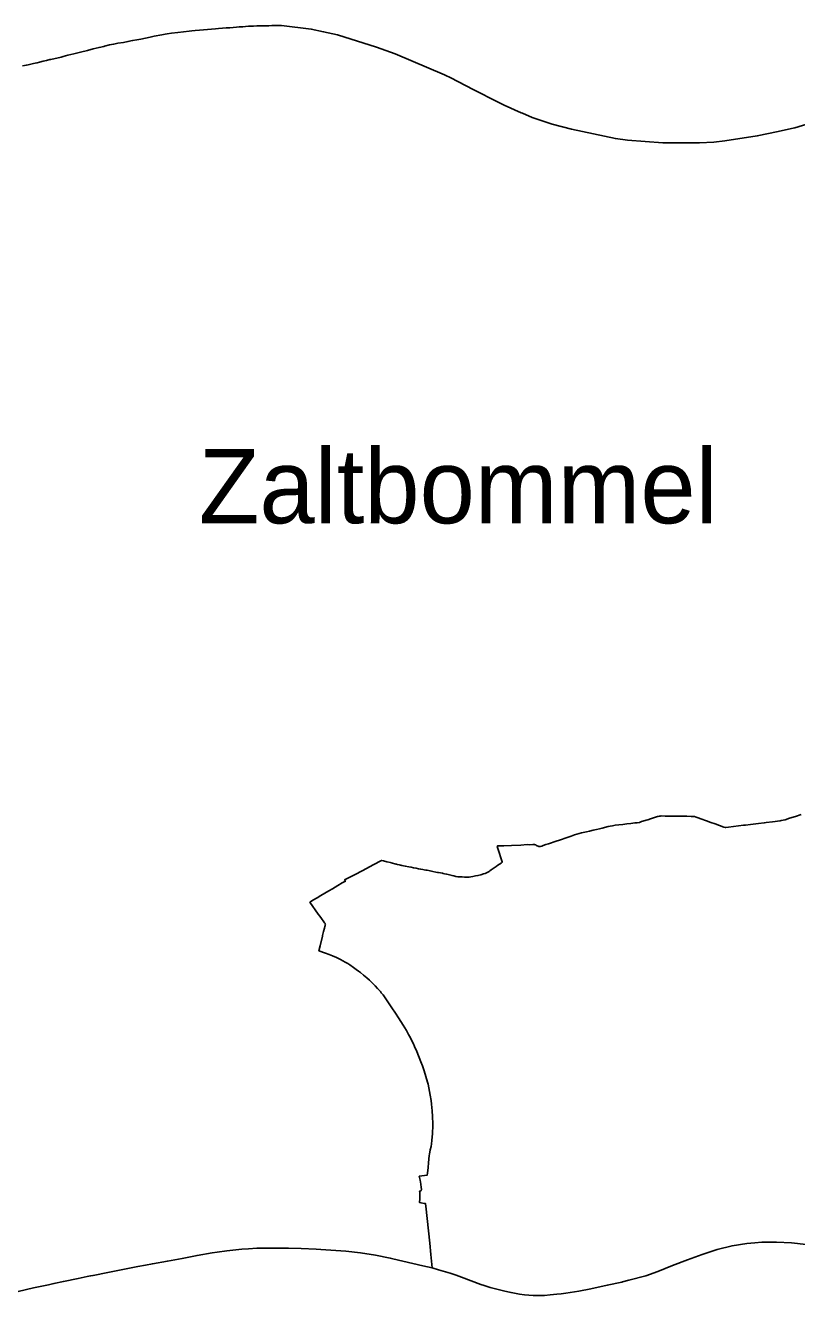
# Model space of a CAD drawing. Extents: x 113371 to 291721, y 393993 to 520143.
# Drawn here: x 138319 to 143509, y 416873 to 425419 of the extents above; entities that cross this region are included whole.
import ezdxf

# ---------------------------------------------------------------- set-up
doc = ezdxf.new("R2010")
doc.units = 0
doc.layers.add('Default', color=7, linetype='Continuous')
doc.layers.add('plaatsnamen', color=7, linetype='Continuous')

msp = doc.modelspace()

# ---------------------------------------------------------------- linework, layer by layer
at = {"layer": 'Default'}
for points in [[(139301.265625, 425366.0325), (139272.555625, 425362.2925), (139258.415625, 425360.2925), (139237.305625, 425356.3025), (139185.835625, 425346.1025), (139158.485625, 425340.3625), (139095.685625, 425327.6925), (139068.735625, 425322.7525), (139039.975625, 425317.1125), (139008.925625, 425311.0525), (138977.775625, 425305.3925), (138940.525625, 425298.7925), (138913.575625, 425293.9525), (138898.645625, 425291.0525), (138884.625625, 425287.6125), (138851.785625, 425279.5925), (138846.865625, 425278.4725), (138814.605625, 425271.1325), (138775.585625, 425261.2225), (138736.615625, 425251.3125), (138690.405625, 425240.1425), (138644.995625, 425228.5925), (138605.225625, 425218.5225), (138572.735625, 425210.5525), (138558.425625, 425206.6525), (138488.975625, 425190.7925), (138483.985625, 425189.4125), (138461.015625, 425184.3125), (138437.445625, 425178.1925), (138413.925625, 425172.2125), (138397.695625, 425168.5325), (138383.685625, 425165.0725), (138372.415625, 425162.3525), (138354.205625, 425158.0825), (138338.215625, 425154.2825), (138325.685625, 425152.2925), (138298.225625, 425147.3425)], [(138354.205625, 425158.0825), (138372.415625, 425162.3525), (138383.685625, 425165.0725), (138397.695625, 425168.5325), (138413.925625, 425172.2125), (138437.445625, 425178.1925), (138461.015625, 425184.3125), (138483.985625, 425189.4125), (138488.975625, 425190.7925), (138558.425625, 425206.6525), (138572.735625, 425210.5525), (138605.225625, 425218.5225), (138644.995625, 425228.5925), (138690.405625, 425240.1425), (138736.615625, 425251.3125), (138775.585625, 425261.2225), (138814.605625, 425271.1325), (138846.865625, 425278.4725), (138851.785625, 425279.5925), (138884.625625, 425287.6125), (138898.645625, 425291.0525), (138913.575625, 425293.9525), (138940.525625, 425298.7925), (138977.775625, 425305.3925), (139008.925625, 425311.0525), (139039.975625, 425317.1125), (139068.735625, 425322.7525), (139095.685625, 425327.6925), (139158.485625, 425340.3625), (139185.835625, 425346.1025), (139237.305625, 425356.3025), (139258.415625, 425360.2925), (139272.555625, 425362.2925), (139301.265625, 425366.0325), (139343.525625, 425371.3725), (139383.025625, 425376.5325), (139421.635625, 425381.5025), (139438.215625, 425383.1125)], [(141138.875625, 425087.6325), (140806.155625, 425227.5025), (140681.085625, 425272.8225), (140418.285625, 425356.1225), (140325.295625, 425376.2825), (140242.585625, 425394.2125), (140042.085625, 425419.3625), (140022.125625, 425418.4725), (139999.185625, 425418.0725), (139977.995625, 425417.7725), (139957.705625, 425417.3825), (139940.715625, 425416.7725), (139919.465625, 425416.3825), (139899.125625, 425416.0925), (139877.035625, 425415.4925), (139853.945625, 425414.9325), (139836.805625, 425414.6625), (139820.615625, 425413.6525), (139799.725625, 425412.0125), (139781.095625, 425410.7425), (139758.355625, 425409.0325), (139738.275625, 425407.5925), (139716.285625, 425405.9525), (139693.905625, 425403.9425), (139669.075625, 425402.3825), (139644.845625, 425400.4625), (139619.115625, 425398.5425), (139599.035625, 425396.9025), (139571.755625, 425394.5225), (139544.825625, 425392.1325), (139517.395625, 425389.8025), (139489.675625, 425387.5125), (139460.895625, 425385.0625), (139438.215625, 425383.1125), (139421.635625, 425381.5025), (139383.025625, 425376.5325), (139343.525625, 425371.3725), (139301.265625, 425366.0325)], [(139438.215625, 425383.1125), (139460.895625, 425385.0625), (139489.675625, 425387.5125), (139517.395625, 425389.8025), (139544.825625, 425392.1325), (139571.755625, 425394.5225), (139599.035625, 425396.9025), (139619.115625, 425398.5425), (139644.845625, 425400.4625), (139669.075625, 425402.3825), (139693.905625, 425403.9425), (139716.285625, 425405.9525), (139738.275625, 425407.5925), (139758.355625, 425409.0325), (139781.095625, 425410.7425), (139799.725625, 425412.0125), (139820.615625, 425413.6525), (139836.805625, 425414.6625), (139853.945625, 425414.9325), (139877.035625, 425415.4925), (139899.125625, 425416.0925), (139919.465625, 425416.3825), (139940.715625, 425416.7725), (139957.705625, 425417.3825), (139977.995625, 425417.7725), (139999.185625, 425418.0725), (140022.125625, 425418.4725), (140042.085625, 425419.3625), (140242.585625, 425394.2125), (140325.295625, 425376.2825), (140418.285625, 425356.1225), (140681.085625, 425272.8225), (140806.155625, 425227.5025), (141138.875625, 425087.6325), (141147.575625, 425083.1625), (141177.265625, 425067.9125), (141337.445625, 424985.6325), (141495.245625, 424904.1225)], [(138298.225625, 425147.3425), (138325.685625, 425152.2925), (138338.215625, 425154.2825), (138354.205625, 425158.0825)], [(143755.485625, 424807.6025), (143498.085625, 424729.8025), (143474.845625, 424724.8625), (143385.995625, 424705.9525), (143244.285625, 424675.7925), (143026.015625, 424642.0825), (142952.685625, 424634.5925), (142855.895625, 424629.1425), (142799.045625, 424629.1625), (142608.115625, 424629.2325), (142371.875625, 424648.0225), (142290.035625, 424657.5625), (141994.255625, 424720.2725), (141863.845625, 424755.2625), (141755.985625, 424790.8125), (141728.415625, 424800.2025), (141664.665625, 424828.0625), (141655.935625, 424831.8825), (141541.905625, 424883.1425), (141495.245625, 424904.1225), (141337.445625, 424985.6325), (141177.265625, 425067.9125), (141147.575625, 425083.1625), (141138.875625, 425087.6325)], [(141495.245625, 424904.1225), (141541.905625, 424883.1425), (141655.935625, 424831.8825), (141664.665625, 424828.0625), (141728.415625, 424800.2025), (141755.985625, 424790.8125), (141863.845625, 424755.2625), (141994.255625, 424720.2725), (142290.035625, 424657.5625), (142371.875625, 424648.0225), (142608.115625, 424629.2325), (142799.045625, 424629.1625), (142855.895625, 424629.1425), (142952.685625, 424634.5925), (143026.015625, 424642.0825), (143244.285625, 424675.7925), (143385.995625, 424705.9525), (143474.845625, 424724.8625), (143498.085625, 424729.8025), (143755.485625, 424807.6025)], [(141779.245625, 419893.8925), (141783.885625, 419893.8925), (141794.665625, 419896.9625), (141803.615625, 419900.4325), (141821.995625, 419907.1925), (141840.015625, 419912.6725), (141890.015625, 419930.4925), (141912.195625, 419937.6925), (141964.845625, 419955.6425), (141991.115625, 419964.7025), (142013.145625, 419972.1825), (142029.825625, 419977.3525), (142045.125625, 419981.8925), (142062.095625, 419986.2025), (142094.735625, 419993.1925), (142114.445625, 419997.9325), (142140.935625, 420004.6825), (142162.855625, 420010.0525), (142181.345625, 420014.4925), (142200.315625, 420019.2325), (142241.615625, 420028.3625), (142253.255625, 420030.7625), (142269.955625, 420034.3125), (142287.495625, 420037.2525), (142312.285625, 420040.1225), (142338.685625, 420043.4625), (142366.605625, 420046.7925), (142394.265625, 420049.6525), (142419.955625, 420053.0425), (142436.265625, 420054.9425), (142451.105625, 420057.1425), (142460.965625, 420060.5025), (142466.065625, 420062.0525), (142474.195625, 420064.3225), (142495.745625, 420070.9025), (142507.825625, 420074.6925), (142525.465625, 420080.3925), (142572.875625, 420095.6325)], [(143050.675625, 420024.8525), (143050.185625, 420024.7925), (143032.385625, 420022.4925), (143029.155625, 420022.0725), (143029.155625, 420022.0625), (143020.205625, 420025.3325), (142990.665625, 420036.0625), (142961.145625, 420046.5225), (142932.855625, 420056.6225), (142901.685625, 420067.7025), (142888.815625, 420072.2725), (142878.095625, 420076.0925), (142832.345625, 420092.3525), (142822.895625, 420095.7125), (142820.605625, 420096.5325), (142814.065625, 420096.7225), (142798.545625, 420097.1825), (142771.045625, 420098.0125), (142731.365625, 420099.1925), (142701.265625, 420098.7525), (142659.505625, 420099.7225), (142624.815625, 420099.6625), (142597.105625, 420100.0325), (142590.565625, 420099.8225), (142585.385625, 420098.9125), (142577.965625, 420097.0125), (142572.875625, 420095.6325), (142525.465625, 420080.3925), (142507.825625, 420074.6925), (142495.745625, 420070.9025), (142474.195625, 420064.3225), (142466.065625, 420062.0525), (142460.965625, 420060.5025), (142451.105625, 420057.1425), (142436.265625, 420054.9425), (142419.955625, 420053.0425), (142394.265625, 420049.6525), (142366.605625, 420046.7925)], [(142572.875625, 420095.6325), (142577.965625, 420097.0125), (142585.385625, 420098.9125), (142590.565625, 420099.8225), (142597.105625, 420100.0325), (142624.815625, 420099.6625), (142659.505625, 420099.7225), (142701.265625, 420098.7525), (142731.365625, 420099.1925), (142771.045625, 420098.0125), (142798.545625, 420097.1825), (142814.065625, 420096.7225), (142820.605625, 420096.5325), (142822.895625, 420095.7125), (142832.345625, 420092.3525), (142878.095625, 420076.0925), (142888.815625, 420072.2725), (142901.685625, 420067.7025), (142932.855625, 420056.6225), (142961.145625, 420046.5225), (142990.665625, 420036.0625), (143020.205625, 420025.3325), (143029.155625, 420022.0625), (143029.155625, 420022.0725), (143032.385625, 420022.4925), (143050.185625, 420024.7925), (143050.675625, 420024.8525), (143152.135625, 420037.9325), (143165.445625, 420038.9625), (143199.095625, 420043.5225), (143252.145625, 420049.9025), (143290.585625, 420054.7425), (143291.875625, 420054.9125), (143304.385625, 420056.4825), (143304.955625, 420056.5625), (143347.875625, 420061.6125), (143398.275625, 420068.4325), (143405.795625, 420069.6925)], [(143540.075625, 420109.6925), (143500.735625, 420097.4925), (143460.325625, 420084.3125), (143433.085625, 420075.1925), (143405.795625, 420069.6925), (143398.275625, 420068.4325), (143347.875625, 420061.6125), (143304.955625, 420056.5625), (143304.385625, 420056.4825), (143291.875625, 420054.9125), (143290.585625, 420054.7425), (143252.145625, 420049.9025), (143199.095625, 420043.5225), (143165.445625, 420038.9625), (143152.135625, 420037.9325), (143050.675625, 420024.8525)], [(143405.795625, 420069.6925), (143433.085625, 420075.1925), (143460.325625, 420084.3125), (143500.735625, 420097.4925), (143540.075625, 420109.6925)], [(142366.605625, 420046.7925), (142338.685625, 420043.4625), (142312.285625, 420040.1225), (142287.495625, 420037.2525), (142269.955625, 420034.3125), (142253.255625, 420030.7625), (142241.615625, 420028.3625), (142200.315625, 420019.2325), (142181.345625, 420014.4925), (142162.855625, 420010.0525), (142140.935625, 420004.6825), (142114.445625, 419997.9325), (142094.735625, 419993.1925), (142062.095625, 419986.2025), (142045.125625, 419981.8925), (142029.825625, 419977.3525), (142013.145625, 419972.1825), (141991.115625, 419964.7025), (141964.845625, 419955.6425), (141912.195625, 419937.6925), (141890.015625, 419930.4925), (141840.015625, 419912.6725), (141821.995625, 419907.1925), (141803.615625, 419900.4325), (141794.665625, 419896.9625), (141783.885625, 419893.8925), (141779.245625, 419893.8925), (141775.135625, 419895.2625), (141769.445625, 419897.1625), (141763.755625, 419899.5825), (141758.145625, 419902.5425), (141752.875625, 419904.9625), (141749.085625, 419906.4325), (141743.915625, 419907.3825), (141739.695625, 419907.9125), (141734.855625, 419907.9125), (141710.775625, 419907.0625), (141696.745625, 419907.4825)], [(141696.745625, 419907.4825), (141652.645625, 419904.8625), (141589.235625, 419902.0925), (141538.275625, 419900.1025), (141494.985625, 419899.1225), (141496.235625, 419895.4525), (141494.195625, 419895.3625), (141494.435625, 419894.6325), (141505.195625, 419861.6425), (141520.745625, 419811.0425), (141526.885625, 419791.8925), (141527.055625, 419791.3625), (141528.055625, 419788.2625), (141520.135625, 419782.9525), (141510.205625, 419775.8925), (141498.685625, 419768.1425), (141486.655625, 419759.8925), (141472.875625, 419750.3525), (141453.975625, 419737.3325), (141445.455625, 419731.5225), (141439.195625, 419727.0925), (141434.575625, 419723.8125), (141425.515625, 419719.2525), (141413.945625, 419713.6025), (141411.295625, 419712.6625), (141401.935625, 419710.0525), (141382.775625, 419704.4825), (141364.555625, 419699.1125), (141348.855625, 419696.5725), (141329.495625, 419693.1525), (141315.395625, 419690.9125), (141306.035625, 419689.4525), (141288.745625, 419688.5725), (141274.645625, 419688.9325), (141257.105625, 419689.6125), (141236.665625, 419690.3425), (141228.375625, 419690.8325), (141215.685625, 419692.6325)], [(141382.775625, 419704.4825), (141401.935625, 419710.0525), (141411.295625, 419712.6625), (141413.945625, 419713.6025), (141425.515625, 419719.2525), (141434.575625, 419723.8125), (141439.195625, 419727.0925), (141445.455625, 419731.5225), (141453.975625, 419737.3325), (141472.875625, 419750.3525), (141486.655625, 419759.8925), (141498.685625, 419768.1425), (141510.205625, 419775.8925), (141520.135625, 419782.9525), (141528.055625, 419788.2625), (141527.055625, 419791.3625), (141526.885625, 419791.8925), (141520.745625, 419811.0425), (141505.195625, 419861.6425), (141494.435625, 419894.6325), (141494.195625, 419895.3625), (141496.235625, 419895.4525), (141494.985625, 419899.1225), (141538.275625, 419900.1025), (141589.235625, 419902.0925), (141652.645625, 419904.8625), (141696.745625, 419907.4825), (141710.775625, 419907.0625), (141734.855625, 419907.9125), (141739.695625, 419907.9125), (141743.915625, 419907.3825), (141749.085625, 419906.4325), (141752.875625, 419904.9625), (141758.145625, 419902.5425), (141763.755625, 419899.5825), (141769.445625, 419897.1625), (141775.135625, 419895.2625), (141779.245625, 419893.8925)], [(140327.305625, 419387.4725), (140310.785625, 419410.5925), (140299.895625, 419425.9825), (140289.765625, 419440.5725), (140233.665625, 419520.8425), (140234.835625, 419521.5425), (140237.345625, 419523.0225), (140253.695625, 419532.6925), (140282.475625, 419549.7325), (140307.205625, 419564.3725), (140333.775625, 419580.0925), (140361.045625, 419596.2325), (140385.625625, 419610.7825), (140420.395625, 419631.3525), (140451.575625, 419649.8025), (140459.275625, 419654.3625), (140472.195625, 419661.1125), (140466.545625, 419669.4325), (140466.395625, 419669.6525), (140532.665625, 419704.5225), (140588.755625, 419734.2725), (140658.325625, 419771.0625), (140716.265625, 419801.5525), (140728.125625, 419798.3925), (140751.695625, 419792.4425), (140775.175625, 419786.2825), (140777.455625, 419785.6825), (140779.625625, 419785.1225), (140813.005625, 419776.3925), (140819.095625, 419774.8325), (140821.025625, 419774.3425), (140836.415625, 419770.4225), (140839.515625, 419769.6325), (140842.175625, 419769.0725), (140844.695625, 419768.5525), (140851.955625, 419767.0325), (140852.215625, 419766.9825), (140875.375625, 419762.5825)], [(140777.455625, 419785.6825), (140775.175625, 419786.2825), (140751.695625, 419792.4425), (140728.125625, 419798.3925), (140716.265625, 419801.5525), (140658.325625, 419771.0625), (140588.755625, 419734.2725), (140532.665625, 419704.5225), (140466.395625, 419669.6525), (140466.545625, 419669.4325), (140472.195625, 419661.1125), (140459.275625, 419654.3625), (140451.575625, 419649.8025), (140420.395625, 419631.3525), (140385.625625, 419610.7825), (140361.045625, 419596.2325), (140333.775625, 419580.0925), (140307.205625, 419564.3725), (140282.475625, 419549.7325), (140253.695625, 419532.6925), (140237.345625, 419523.0225), (140234.835625, 419521.5425), (140233.665625, 419520.8425), (140289.765625, 419440.5725), (140299.895625, 419425.9825), (140310.785625, 419410.5925), (140327.305625, 419387.4725), (140331.535625, 419381.4825), (140335.535625, 419375.8225), (140336.795625, 419374.0425), (140337.975625, 419372.3625), (140336.945625, 419368.1825), (140336.715625, 419367.2725), (140335.045625, 419360.5225), (140333.885625, 419355.8525), (140331.275625, 419345.3525), (140325.555625, 419322.2925), (140318.855625, 419295.3325)], [(141215.685625, 419692.6325), (141201.855625, 419696.4825), (141189.775625, 419699.5425), (141172.595625, 419704.2625), (141163.155625, 419706.9425), (141153.575625, 419709.0825), (141139.835625, 419711.7425), (141130.045625, 419713.9325), (141125.555625, 419714.8525), (141113.265625, 419716.7525), (141098.735625, 419719.2625), (141092.535625, 419720.2425), (141081.145625, 419722.4325), (141061.175625, 419726.4725), (141041.895625, 419730.3425), (141022.615625, 419734.5225), (141013.125625, 419736.3125), (141002.185625, 419738.3625), (140992.395625, 419740.1525), (140978.515625, 419742.6125), (140965.075625, 419744.9125), (140948.795625, 419748.1825), (140931.365625, 419751.4525), (140931.285625, 419751.4725), (140914.385625, 419754.8225), (140898.105625, 419758.0925), (140875.375625, 419762.5825), (140852.215625, 419766.9825), (140851.955625, 419767.0325), (140844.695625, 419768.5525), (140842.175625, 419769.0725), (140839.515625, 419769.6325), (140836.415625, 419770.4225), (140821.025625, 419774.3425), (140819.095625, 419774.8325), (140813.005625, 419776.3925), (140779.625625, 419785.1225), (140777.455625, 419785.6825)], [(140875.375625, 419762.5825), (140898.105625, 419758.0925), (140914.385625, 419754.8225), (140931.285625, 419751.4725), (140931.365625, 419751.4525), (140948.795625, 419748.1825), (140965.075625, 419744.9125), (140978.515625, 419742.6125), (140992.395625, 419740.1525), (141002.185625, 419738.3625), (141013.125625, 419736.3125), (141022.615625, 419734.5225), (141041.895625, 419730.3425), (141061.175625, 419726.4725), (141081.145625, 419722.4325), (141092.535625, 419720.2425), (141098.735625, 419719.2625), (141113.265625, 419716.7525), (141125.555625, 419714.8525), (141130.045625, 419713.9325), (141139.835625, 419711.7425), (141153.575625, 419709.0825), (141163.155625, 419706.9425), (141172.595625, 419704.2625), (141189.775625, 419699.5425), (141201.855625, 419696.4825), (141215.685625, 419692.6325), (141228.375625, 419690.8325), (141236.665625, 419690.3425), (141257.105625, 419689.6125), (141274.645625, 419688.9325), (141288.745625, 419688.5725), (141306.035625, 419689.4525), (141315.395625, 419690.9125), (141329.495625, 419693.1525), (141348.855625, 419696.5725), (141364.555625, 419699.1125), (141382.775625, 419704.4825)], [(140735.005625, 418883.6625), (140725.865625, 418895.6525), (140713.985625, 418911.2925), (140707.965625, 418919.0225), (140689.065625, 418938.4125), (140671.715625, 418956.8125), (140649.955625, 418979.0825), (140633.625625, 418994.9125), (140616.265625, 419010.4525), (140594.835625, 419028.4825), (140573.445625, 419046.1625), (140560.145625, 419056.3725), (140544.455625, 419067.8025), (140526.165625, 419080.6725), (140501.235625, 419098.4525), (140487.705625, 419107.0325), (140470.625625, 419117.3625), (140455.325625, 419125.9125), (140439.455625, 419134.2625), (140411.555625, 419147.2125), (140385.705625, 419158.2625), (140362.285625, 419167.6525), (140338.415625, 419176.5425), (140294.355625, 419192.8225), (140302.245625, 419225.8725), (140317.815625, 419291.1425), (140318.855625, 419295.3325), (140325.555625, 419322.2925), (140331.275625, 419345.3525), (140333.885625, 419355.8525), (140335.045625, 419360.5225), (140336.715625, 419367.2725), (140336.945625, 419368.1825), (140337.975625, 419372.3625), (140336.795625, 419374.0425), (140335.535625, 419375.8225), (140331.535625, 419381.4825), (140327.305625, 419387.4725)], [(140318.855625, 419295.3325), (140317.815625, 419291.1425), (140302.245625, 419225.8725), (140294.355625, 419192.8225), (140338.415625, 419176.5425), (140362.285625, 419167.6525), (140385.705625, 419158.2625), (140411.555625, 419147.2125), (140439.455625, 419134.2625), (140455.325625, 419125.9125), (140470.625625, 419117.3625), (140487.705625, 419107.0325), (140501.235625, 419098.4525), (140526.165625, 419080.6725), (140544.455625, 419067.8025), (140560.145625, 419056.3725), (140573.445625, 419046.1625), (140594.835625, 419028.4825), (140616.265625, 419010.4525), (140633.625625, 418994.9125), (140649.955625, 418979.0825), (140671.715625, 418956.8125), (140689.065625, 418938.4125), (140707.965625, 418919.0225), (140713.985625, 418911.2925), (140725.865625, 418895.6525), (140735.005625, 418883.6625), (140757.465625, 418850.6525), (140784.485625, 418810.2525), (140809.035625, 418773.5325), (140830.435625, 418741.6425), (140860.685625, 418692.3525), (140883.015625, 418656.1725), (140897.865625, 418630.5125), (140910.835625, 418606.4125), (140920.355625, 418588.3525), (140931.155625, 418566.3125), (140938.395625, 418550.2125)], [(141033.485625, 417791.5825), (141036.345625, 417814.7125), (141038.295625, 417825.3025), (141043.635625, 417853.2925), (141048.635625, 417877.2825), (141051.385625, 417894.7525), (141054.205625, 417917.1025), (141056.825625, 417941.8525), (141058.755625, 417961.0325), (141061.385625, 418019.3125), (141061.595625, 418030.5825), (141058.705625, 418076.4825), (141056.295625, 418117.7125), (141054.875625, 418135.6125), (141051.795625, 418162.9625), (141049.245625, 418182.4525), (141048.735625, 418186.3525), (141042.165625, 418222.6825), (141029.125625, 418295.0625), (141026.925625, 418302.9325), (141018.325625, 418332.3225), (141009.055625, 418363.4625), (141000.135625, 418391.0325), (140990.135625, 418419.4325), (140980.665625, 418445.7125), (140952.725625, 418515.5125), (140938.395625, 418550.2125), (140931.155625, 418566.3125), (140920.355625, 418588.3525), (140910.835625, 418606.4125), (140897.865625, 418630.5125), (140883.015625, 418656.1725), (140860.685625, 418692.3525), (140830.435625, 418741.6425), (140809.035625, 418773.5325), (140784.485625, 418810.2525), (140757.465625, 418850.6525), (140735.005625, 418883.6625)], [(140938.395625, 418550.2125), (140952.725625, 418515.5125), (140980.665625, 418445.7125), (140990.135625, 418419.4325), (141000.135625, 418391.0325), (141009.055625, 418363.4625), (141018.325625, 418332.3225), (141026.925625, 418302.9325), (141029.125625, 418295.0625), (141042.165625, 418222.6825), (141048.735625, 418186.3525), (141049.245625, 418182.4525), (141051.795625, 418162.9625), (141054.875625, 418135.6125), (141056.295625, 418117.7125), (141058.705625, 418076.4825), (141061.595625, 418030.5825), (141061.385625, 418019.3125), (141058.755625, 417961.0325), (141056.825625, 417941.8525), (141054.205625, 417917.1025), (141051.385625, 417894.7525), (141048.635625, 417877.2825), (141043.635625, 417853.2925), (141038.295625, 417825.3025), (141036.345625, 417814.7125), (141033.485625, 417791.5825), (141031.515625, 417766.3625), (141028.225625, 417734.0225), (141024.785625, 417695.9925), (141023.605625, 417683.5925), (140969.755625, 417676.4425), (140974.835625, 417649.0725), (140979.935625, 417622.1425), (140983.185625, 417600.6425), (140984.935625, 417589.5925), (140984.655625, 417587.2325), (140984.085625, 417585.6025)], [(140573.355625, 417160.6425), (140673.835625, 417145.7225), (140774.305625, 417125.0825), (140791.475625, 417120.9525), (140993.405625, 417074.0625), (141057.155625, 417059.5525), (141047.965625, 417149.8625), (141039.915625, 417226.3425), (141031.265625, 417308.4825), (141013.225625, 417475.4125), (141011.435625, 417491.9325), (141002.415625, 417493.1225), (140981.735625, 417496.6425), (140971.685625, 417498.8525), (140971.825625, 417503.8225), (140972.305625, 417520.6625), (140972.415625, 417524.2425), (140972.865625, 417554.5425), (140972.835625, 417560.0525), (140972.315625, 417566.9225), (140970.805625, 417575.4325), (140975.995625, 417575.2925), (140979.435625, 417577.6625), (140980.705625, 417578.9025), (140982.005625, 417581.0425), (140983.265625, 417583.6025), (140984.085625, 417585.6025), (140984.655625, 417587.2325), (140984.935625, 417589.5925), (140983.185625, 417600.6425), (140979.935625, 417622.1425), (140974.835625, 417649.0725), (140969.755625, 417676.4425), (141023.605625, 417683.5925), (141024.785625, 417695.9925), (141028.225625, 417734.0225), (141031.515625, 417766.3625), (141033.485625, 417791.5825)], [(140984.085625, 417585.6025), (140983.265625, 417583.6025), (140982.005625, 417581.0425), (140980.705625, 417578.9025), (140979.435625, 417577.6625), (140975.995625, 417575.2925), (140970.805625, 417575.4325), (140972.315625, 417566.9225), (140972.835625, 417560.0525), (140972.865625, 417554.5425), (140972.415625, 417524.2425), (140972.305625, 417520.6625), (140971.825625, 417503.8225), (140971.685625, 417498.8525), (140981.735625, 417496.6425), (141002.415625, 417493.1225), (141011.435625, 417491.9325), (141013.225625, 417475.4125), (141031.265625, 417308.4825), (141039.915625, 417226.3425), (141047.965625, 417149.8625), (141057.155625, 417059.5525), (141099.915625, 417046.9825), (141177.645625, 417023.2225), (141217.965625, 417010.2425), (141253.015625, 416997.9025), (141382.685625, 416947.9725), (141405.575625, 416940.0825), (141447.465625, 416927.7625), (141545.205625, 416902.9725), (141577.405625, 416895.6825), (141587.855625, 416893.3225), (141644.115625, 416882.4025), (141677.185625, 416878.2025), (141735.225625, 416874.7725), (141781.565625, 416873.1225), (141813.185625, 416874.3925), (141851.085625, 416877.4525)], [(141851.085625, 416877.4525), (141896.305625, 416881.7625), (141924.285625, 416885.3325), (141956.865625, 416889.8925), (142043.355625, 416903.8525), (142123.645625, 416919.3525), (142235.155625, 416942.4825), (142333.155625, 416964.1525), (142337.415625, 416965.1025), (142379.335625, 416976.3925), (142493.235625, 417006.7825), (142574.285625, 417034.7525), (142674.285625, 417074.7525), (142774.285625, 417113.7525), (142874.285625, 417149.7525), (142974.285625, 417183.7525), (143074.285625, 417208.7525), (143174.285625, 417224.7525), (143226.845625, 417228.4325), (143274.285625, 417231.7525), (143374.285625, 417232.7525), (143474.285625, 417228.7525), (143574.285625, 417216.7525)], [(138270.215625, 416901.5325), (138373.215625, 416925.3925), (138473.725625, 416945.8225), (138510.065625, 416953.6625), (138574.255625, 416968.1325), (138674.425625, 416989.1225), (138733.485625, 417001.1825), (138757.235625, 417006.0225), (138774.005625, 417009.4425), (138873.575625, 417029.3725), (138930.595625, 417040.2925), (138974.035625, 417048.5425), (139074.495625, 417068.8525), (139127.705625, 417078.8825), (139173.935625, 417087.5225), (139274.015625, 417105.5425), (139325.455625, 417114.6825), (139373.965625, 417123.0625), (139474.555625, 417142.9925), (139574.505625, 417159.8825), (139609.005625, 417165.1525), (139674.205625, 417175.1125), (139774.285625, 417184.8825), (139819.495625, 417187.8025), (139875.255625, 417191.2325), (139973.555625, 417193.0025), (140073.885625, 417193.0025), (140090.145625, 417192.7425), (140174.475625, 417190.0725), (140274.435625, 417185.8825), (140306.165625, 417184.1925), (140374.905625, 417179.7425), (140474.565625, 417172.4725), (140573.355625, 417160.6425)]]:
    msp.add_lwpolyline(points, dxfattribs=at)

# ---------------------------------------------------------------- texts
at = {"layer": 'plaatsnamen'}
msp.add_text('Zaltbommel', height=500, dxfattribs=at).set_placement((139485.305008, 422069.447015))

doc.saveas('drawing.dxf')
